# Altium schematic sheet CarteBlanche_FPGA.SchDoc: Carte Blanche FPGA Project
size A1; DrawnBy: SRKH; Engineer: SRKH; DocumentNumber: 1; Revision: CB500E; SheetNumber: 1; SheetTotal: 1
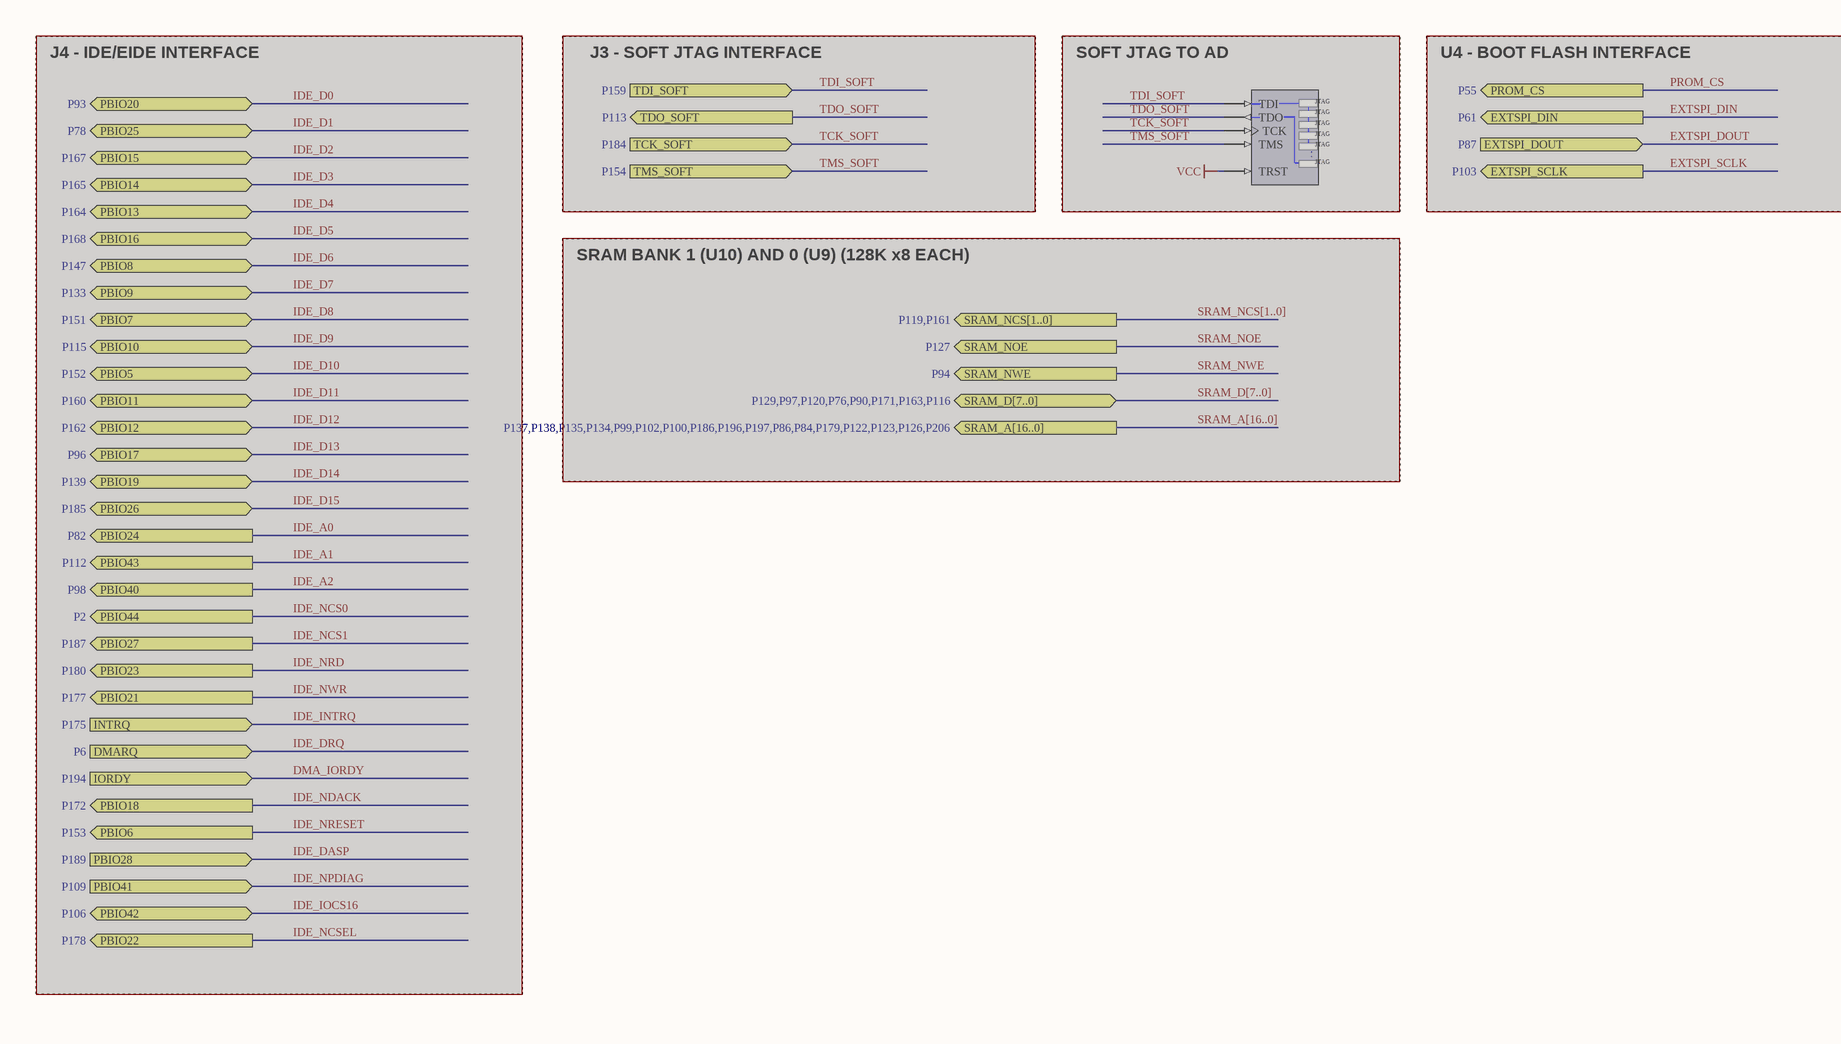
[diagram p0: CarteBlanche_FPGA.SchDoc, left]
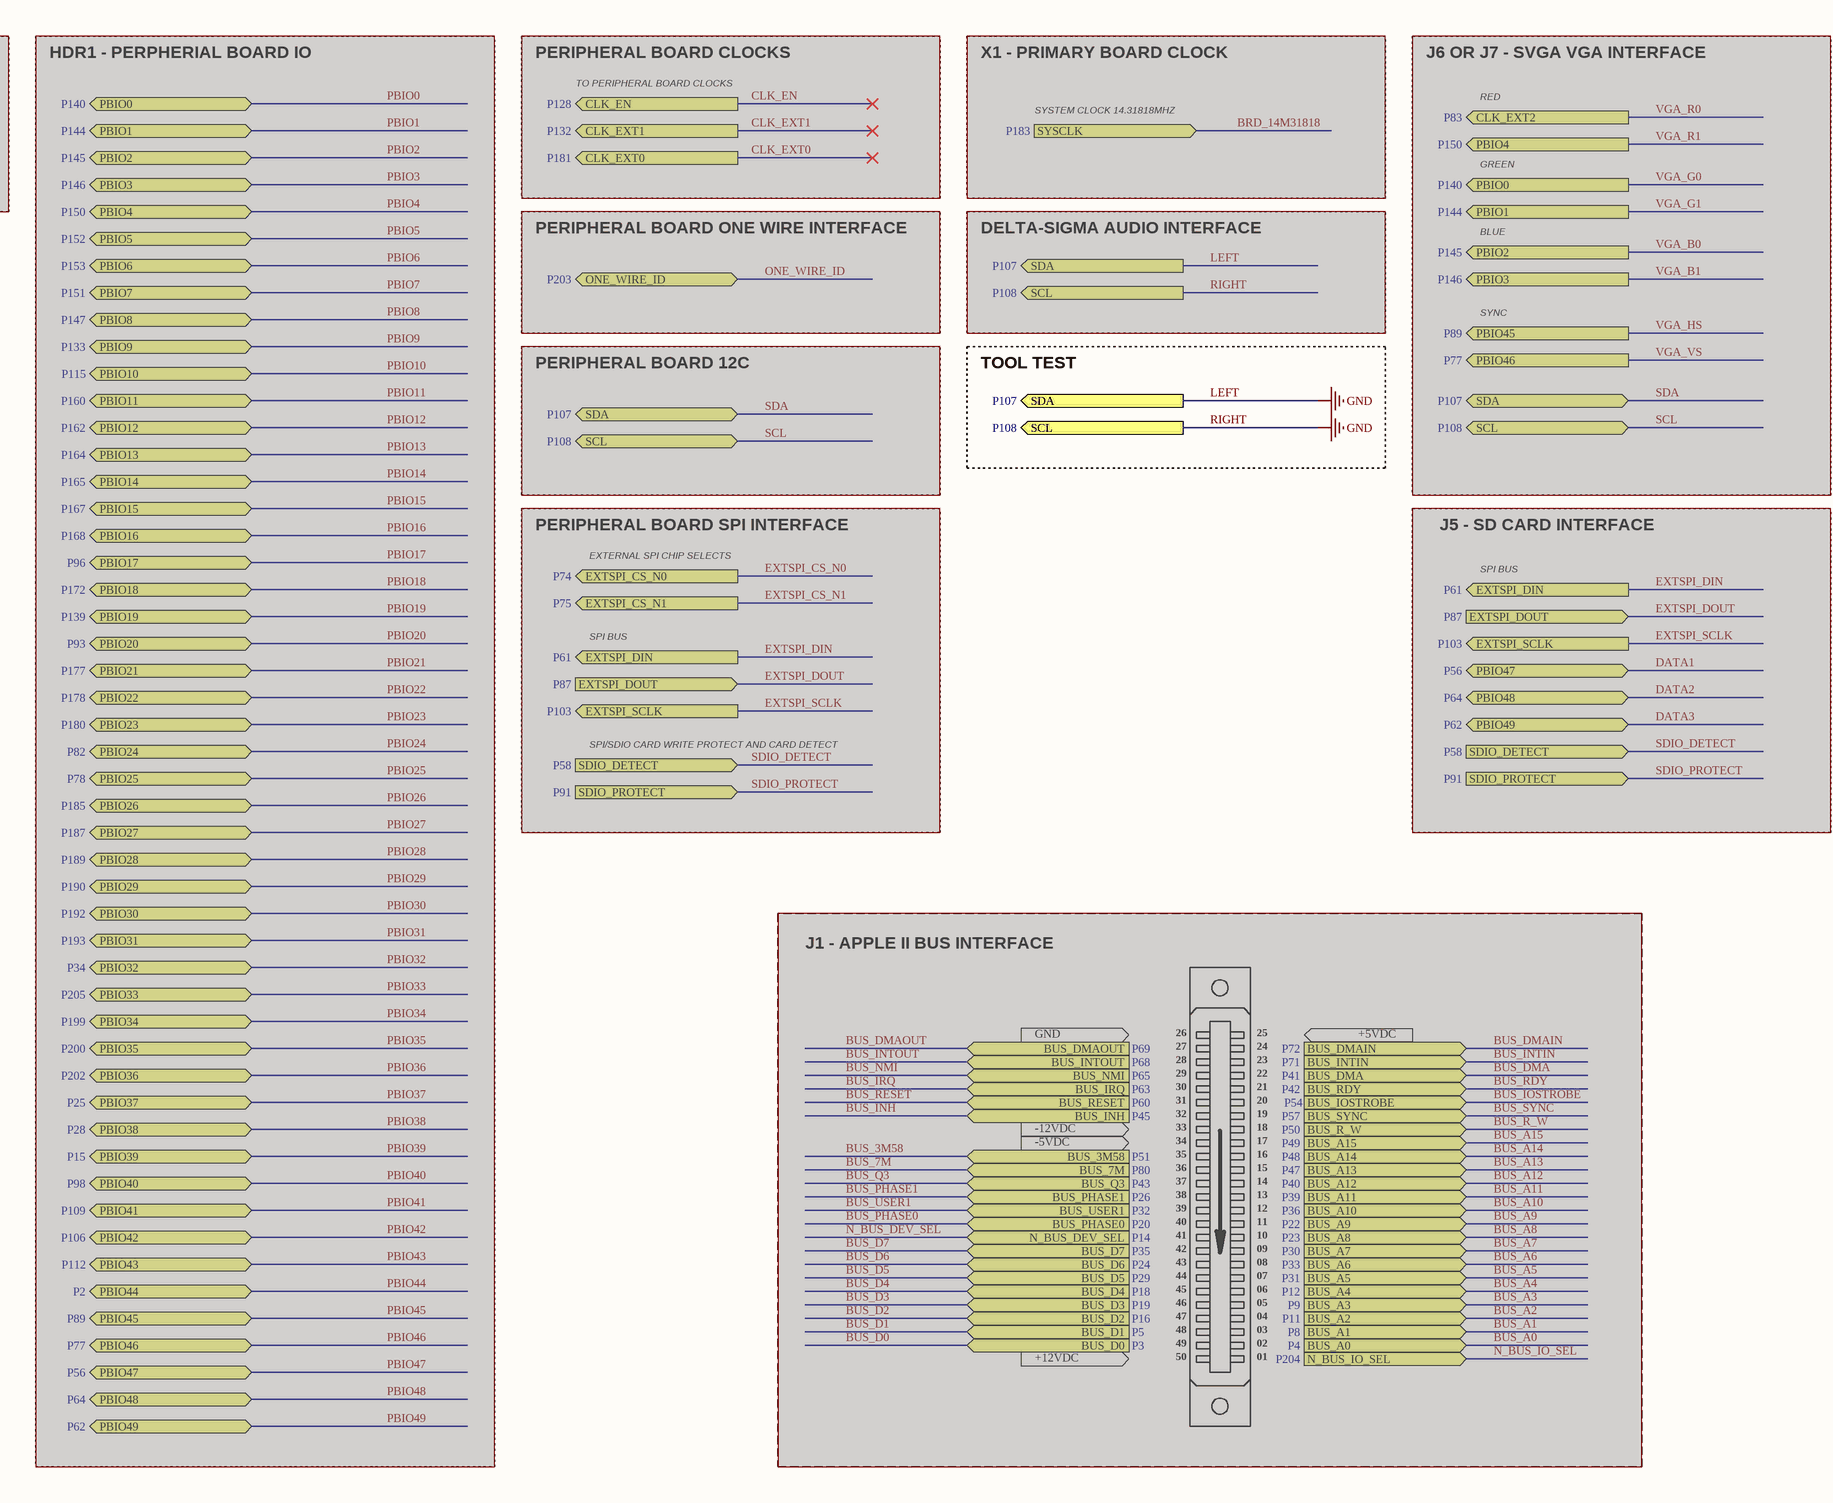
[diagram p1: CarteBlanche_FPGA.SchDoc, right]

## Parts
NEXUS_JTAG_PORT  NEXUS_JTAG_PORT  (value not drawn)  (masked out: inside a compile mask, not in the netlist)

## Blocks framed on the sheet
SOFT JTAG TO AD: NEXUS_JTAG_PORT

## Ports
BUS_3M58 (in, see P51), BUS_7M (in, see P80), BUS_A0 (in, see P4), BUS_A1 (in, see P8), BUS_A2 (in, see P11), BUS_A3 (in, see P9), BUS_A4 (in, see P12), BUS_A5 (in, see P31), BUS_A6 (in, see P33), BUS_A7 (in, see P30), BUS_A8 (in, see P23), BUS_A9 (in, see P22), BUS_A10 (in, see P36), BUS_A11 (in, see P39), BUS_A12 (in, see P40), BUS_A13 (in, see P47), BUS_A14 (in, see P48), BUS_A15 (in, see P49), BUS_D0 (in, see P3), BUS_D1 (in, see P5), BUS_D2 (in, see P16), BUS_D3 (in, see P19), BUS_D4 (in, see P18), BUS_D5 (in, see P29), BUS_D6 (in, see P24), BUS_D7 (in, see P35), BUS_DMA (in, see P41), BUS_DMAIN (in, see P72), BUS_DMAOUT (in, see P69), BUS_INH (in, see P45), BUS_INTIN (in, see P71), BUS_INTOUT (in, see P68), BUS_IOSTROBE (in, see P54), BUS_IRQ (in, see P63), BUS_NMI (in, see P65), BUS_PHASE0 (in, see P20), BUS_PHASE1 (in, see P26), BUS_Q3 (in, see P43), BUS_R_W (in, see P50), BUS_RDY (in, see P42), BUS_RESET (in, see P60), BUS_SYNC (in, see P57), BUS_USER1 (in, see P32), CLK_EN (out, see P128), CLK_EXT0 (out, see P181), CLK_EXT1 (out, see P132), CLK_EXT2 (out, see P83), DMARQ (in, see P6), EXTSPI_CS_N0 (out, see P74), EXTSPI_CS_N1 (out, see P75), EXTSPI_DIN (out, see P61), EXTSPI_DOUT (in, see P87), EXTSPI_SCLK (out, see P103), INTRQ (in, see P175), IORDY (in, see P194), N_BUS_DEV_SEL (in, see P14), N_BUS_IO_SEL (in, see P204), ONE_WIRE_ID (bidir, see P203), PBIO0 (bidir, see P140), PBIO0 (out, see P140), PBIO1 (bidir, see P144), PBIO1 (out, see P144), PBIO2 (bidir, see P145), PBIO2 (out, see P145), PBIO3 (bidir, see P146), PBIO3 (out, see P146), PBIO4 (bidir, see P150), PBIO4 (out, see P150), PBIO5 (bidir, see P152), PBIO6 (bidir, see P153), PBIO6 (out, see P153), PBIO7 (bidir, see P151), PBIO8 (bidir, see P147), PBIO9 (bidir, see P133), PBIO10 (bidir, see P115), PBIO11 (bidir, see P160), PBIO12 (bidir, see P162), PBIO13 (bidir, see P164), PBIO14 (bidir, see P165), PBIO15 (bidir, see P167), PBIO16 (bidir, see P168), PBIO17 (bidir, see P96), PBIO18 (bidir, see P172), PBIO18 (out, see P172), PBIO19 (bidir, see P139), PBIO20 (bidir, see P93), PBIO21 (bidir, see P177), PBIO21 (out, see P177), PBIO22 (bidir, see P178), PBIO22 (out, see P178), PBIO23 (bidir, see P180), PBIO23 (out, see P180), PBIO24 (bidir, see P82), PBIO24 (out, see P82), PBIO25 (bidir, see P78), PBIO26 (bidir, see P185), PBIO27 (bidir, see P187), PBIO27 (out, see P187), PBIO28 (bidir, see P189), PBIO28 (in, see P189), PBIO29 (bidir, see P190), PBIO30 (bidir, see P192), PBIO31 (bidir, see P193), PBIO32 (bidir, see P34), PBIO33 (bidir, see P205), PBIO34 (bidir, see P199), PBIO35 (bidir, see P200), PBIO36 (bidir, see P202), PBIO37 (bidir, see P25), PBIO38 (bidir, see P28), PBIO39 (bidir, see P15), PBIO40 (bidir, see P98), PBIO40 (out, see P98), PBIO41 (bidir, see P109), PBIO41 (in, see P109), PBIO42 (bidir, see P106), PBIO43 (bidir, see P112), PBIO43 (out, see P112), PBIO44 (bidir, see P2), PBIO44 (out, see P2), PBIO45 (bidir, see P89), PBIO45 (out, see P89), PBIO46 (bidir, see P77), PBIO46 (out, see P77), PBIO47 (bidir, see P56), PBIO48 (bidir, see P64), PBIO49 (bidir, see P62), PROM_CS (out, see P55), SCL (bidir, see P108), SCL (out, see P108), SDA (bidir, see P107), SDA (out, see P107), SDIO_DETECT (in, see P58), SDIO_PROTECT (in, see P91), SRAM_A[16..0] (out, see P137,P138,P135,P134,P99,P102,P100,P186,P196,P197,P86,P84,P179,P122,P123,P126,P206), SRAM_D[7..0] (bidir, see P129,P97,P120,P76,P90,P171,P163,P116), SRAM_NCS[1..0] (out, see P119,P161), SRAM_NOE (out, see P127), SRAM_NWE (out, see P94), SYSCLK (in, see P183), TCK_SOFT (in, see P184), TDI_SOFT (in, see P159), TDO_SOFT (out, see P113), TMS_SOFT (in, see P154)

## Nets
LEFT: port SDA, port SCL  [also labelled GND, RIGHT]

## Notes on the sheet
- J4 - IDE/EIDE INTERFACE
- J3 - SOFT JTAG INTERFACE
- U4 - BOOT FLASH INTERFACE
- HDR1 - PERPHERIAL BOARD IO
- PERIPHERAL BOARD CLOCKS
- X1 - PRIMARY BOARD CLOCK
- J6 OR J7 - SVGA VGA INTERFACE
- TO PERIPHERAL BOARD CLOCKS
- SYSTEM CLOCK 14.31818MHZ
- RED
- GREEN
- SRAM BANK 1 (U10) AND 0 (U9) (128K x8 EACH)
- PERIPHERAL BOARD ONE WIRE INTERFACE
- DELTA-SIGMA AUDIO INTERFACE
- BLUE
- SYNC
- PERIPHERAL BOARD 12C
- TOOL TEST
- PERIPHERAL BOARD SPI INTERFACE
- J5 - SD CARD INTERFACE
- EXTERNAL SPI CHIP SELECTS
- SPI BUS
- SPI/SDIO CARD WRITE PROTECT AND CARD DETECT
- J1 - APPLE II BUS INTERFACE
- GND
- 26
- 27
- 28
- 29
- 25
- 24
- 23
- 22
- +5VDC
- -12VDC
- 30
- 31
- 32
- 33
- 34
- 21
- 20
- 19
- 18
- 17
- -5VDC
- 35
- 36
- 37
- 38
- 39
- 16
- 15
- 14
- 13
- 12
- 40
- 41
- 42
- 43
- 44
- 11
- 10
- 09
- 08
- 07
- 45
- 46
- 47
- 48
- 49
- 06
- 05
- 04
- 03
- 02
- +12VDC
- 50
- 01

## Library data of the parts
NEXUS_JTAG_PORT = NEXUS_JTAG_PORT: Soft Nexus-Chain Connector; NEXUS_JTAG_CONNECTOR: True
